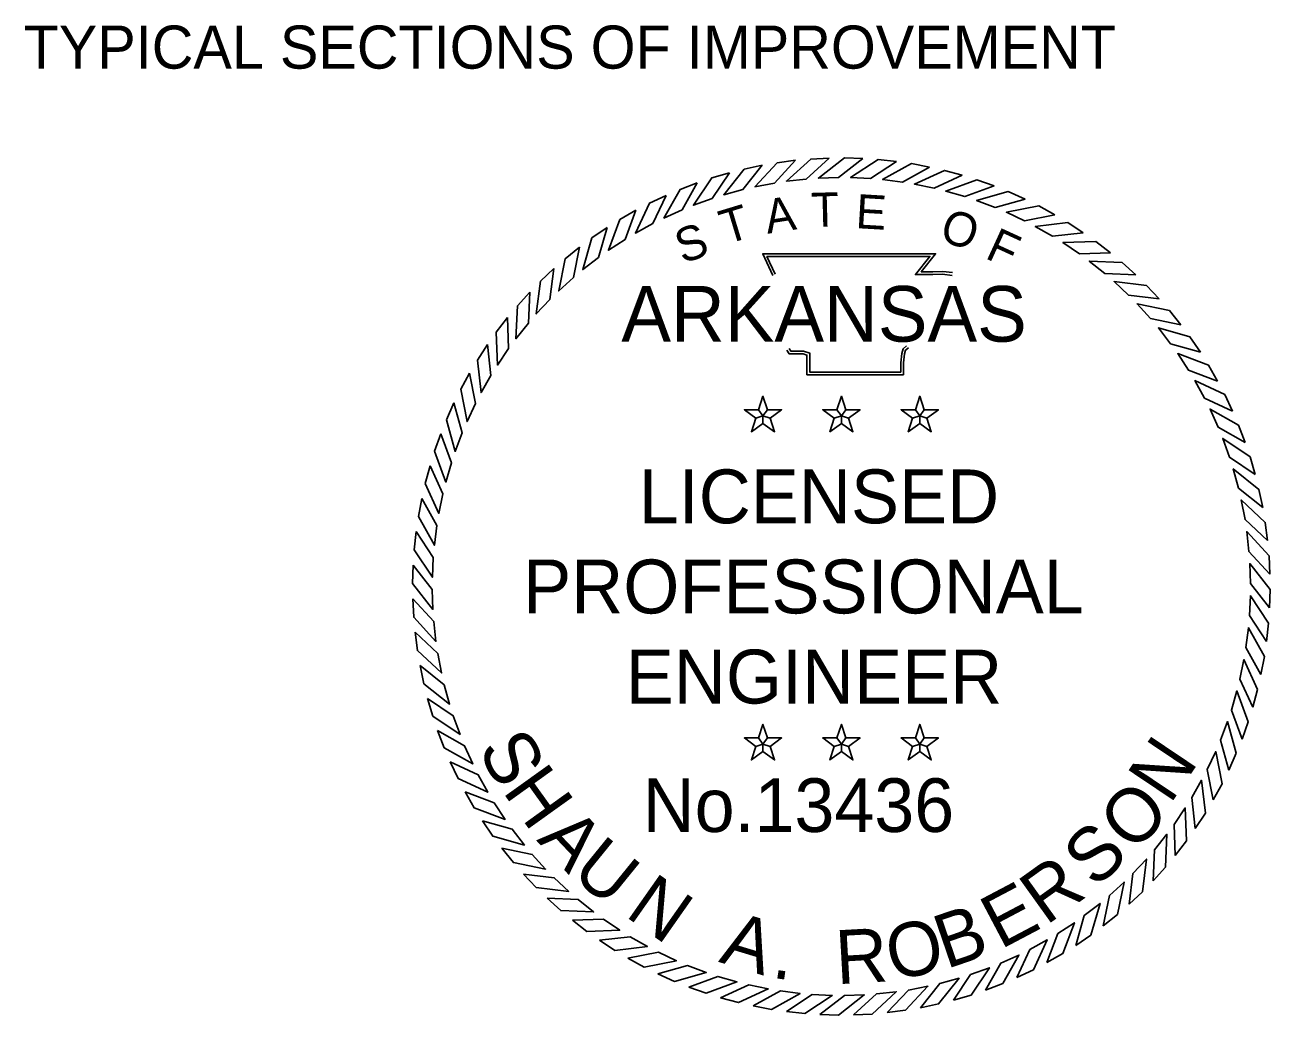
# Model space of a CAD drawing. Extents: x 1001270 to 1003428, y 1840152 to 1842912.
# Drawn here: x 1001411.14 to 1001428.47, y 1840237.95 to 1840251.73 of the extents above; entities that cross this region are included whole.
import ezdxf

# ---------------------------------------------------------------- set-up
doc = ezdxf.new("R2010")
doc.units = 0
doc.layers.add('1', color=7, linetype='Continuous')
doc.layers.add('G-ANNO-SYMB', color=7, linetype='Continuous')

msp = doc.modelspace()

# ---------------------------------------------------------------- linework, layer by layer
at = {"layer": 'G-ANNO-SYMB'}
for points in [[(1001421.401, 1840249.777), (1001421.15, 1840249.724), (1001420.865, 1840249.367), (1001421.132, 1840249.44)], [(1001421.864, 1840249.846), (1001421.61, 1840249.813), (1001421.298, 1840249.478), (1001421.57, 1840249.53)], [(1001422.332, 1840249.877), (1001422.075, 1840249.864), (1001421.738, 1840249.556), (1001422.014, 1840249.586)], [(1001422.8, 1840249.872), (1001422.544, 1840249.88), (1001422.183, 1840249.598), (1001422.46, 1840249.607)], [(1001423.267, 1840249.831), (1001423.012, 1840249.858), (1001422.63, 1840249.606), (1001422.907, 1840249.593)], [(1001423.729, 1840249.752), (1001423.476, 1840249.8), (1001423.076, 1840249.578), (1001423.351, 1840249.543)], [(1001420.944, 1840249.673), (1001420.698, 1840249.6), (1001420.442, 1840249.221), (1001420.703, 1840249.315)], [(1001424.183, 1840249.638), (1001423.935, 1840249.705), (1001423.519, 1840249.515), (1001423.791, 1840249.459)], [(1001424.627, 1840249.489), (1001424.385, 1840249.575), (1001423.955, 1840249.418), (1001424.222, 1840249.341)], [(1001420.497, 1840249.533), (1001420.257, 1840249.441), (1001420.032, 1840249.043), (1001420.285, 1840249.158)], [(1001425.058, 1840249.305), (1001424.823, 1840249.41), (1001424.383, 1840249.287), (1001424.642, 1840249.19)], [(1001420.063, 1840249.358), (1001419.831, 1840249.248), (1001419.637, 1840248.834), (1001419.88, 1840248.967)], [(1001419.643, 1840249.15), (1001419.42, 1840249.022), (1001419.26, 1840248.594), (1001419.492, 1840248.746)], [(1001425.473, 1840249.088), (1001425.248, 1840249.211), (1001424.799, 1840249.123), (1001425.049, 1840249.005)], [(1001419.241, 1840248.909), (1001419.029, 1840248.765), (1001418.903, 1840248.325), (1001419.122, 1840248.495)], [(1001425.869, 1840248.839), (1001425.655, 1840248.979), (1001425.2, 1840248.927), (1001425.441, 1840248.79)], [(1001426.246, 1840248.559), (1001426.042, 1840248.716), (1001425.585, 1840248.7), (1001425.815, 1840248.544)], [(1001418.859, 1840248.638), (1001418.659, 1840248.477), (1001418.568, 1840248.029), (1001418.773, 1840248.216)], [(1001426.598, 1840248.251), (1001426.408, 1840248.423), (1001425.951, 1840248.443), (1001426.168, 1840248.27)], [(1001418.5, 1840248.338), (1001418.313, 1840248.162), (1001418.257, 1840247.708), (1001418.447, 1840247.91)], [(1001426.926, 1840247.916), (1001426.75, 1840248.103), (1001426.296, 1840248.159), (1001426.498, 1840247.969)], [(1001418.165, 1840248.01), (1001417.993, 1840247.82), (1001417.973, 1840247.363), (1001418.146, 1840247.579)], [(1001427.227, 1840247.557), (1001427.066, 1840247.757), (1001426.617, 1840247.848), (1001426.804, 1840247.643)], [(1001417.857, 1840247.657), (1001417.7, 1840247.454), (1001417.716, 1840246.997), (1001417.872, 1840247.226)], [(1001427.498, 1840247.175), (1001427.353, 1840247.387), (1001426.913, 1840247.513), (1001427.083, 1840247.294)], [(1001417.577, 1840247.281), (1001417.437, 1840247.066), (1001417.489, 1840246.612), (1001417.626, 1840246.853)], [(1001427.738, 1840246.773), (1001427.611, 1840246.996), (1001427.182, 1840247.156), (1001427.334, 1840246.924)], [(1001417.328, 1840246.884), (1001417.205, 1840246.659), (1001417.293, 1840246.21), (1001417.411, 1840246.461)], [(1001427.946, 1840246.353), (1001427.837, 1840246.585), (1001427.422, 1840246.779), (1001427.556, 1840246.536)], [(1001417.111, 1840246.469), (1001417.006, 1840246.235), (1001417.129, 1840245.794), (1001417.226, 1840246.054)], [(1001421.411, 1840246.289), (1001421.472, 1840246.374), (1001421.411, 1840246.562), (1001421.35, 1840246.374)], [(1001422.502, 1840246.289), (1001422.563, 1840246.374), (1001422.502, 1840246.562), (1001422.441, 1840246.374)], [(1001423.593, 1840246.289), (1001423.654, 1840246.374), (1001423.593, 1840246.562), (1001423.532, 1840246.374)], [(1001421.411, 1840246.289), (1001421.35, 1840246.374), (1001421.152, 1840246.374), (1001421.312, 1840246.257)], [(1001421.411, 1840246.289), (1001421.312, 1840246.257), (1001421.251, 1840246.069), (1001421.411, 1840246.185)], [(1001421.411, 1840246.289), (1001421.51, 1840246.257), (1001421.671, 1840246.374), (1001421.472, 1840246.374)], [(1001421.411, 1840246.289), (1001421.411, 1840246.185), (1001421.572, 1840246.069), (1001421.51, 1840246.257)], [(1001422.502, 1840246.289), (1001422.441, 1840246.374), (1001422.243, 1840246.374), (1001422.403, 1840246.257)], [(1001422.502, 1840246.289), (1001422.403, 1840246.257), (1001422.342, 1840246.069), (1001422.502, 1840246.185)], [(1001422.502, 1840246.289), (1001422.601, 1840246.257), (1001422.762, 1840246.374), (1001422.563, 1840246.374)], [(1001422.502, 1840246.289), (1001422.502, 1840246.185), (1001422.662, 1840246.069), (1001422.601, 1840246.257)], [(1001423.593, 1840246.289), (1001423.532, 1840246.374), (1001423.334, 1840246.374), (1001423.494, 1840246.257)], [(1001423.593, 1840246.289), (1001423.494, 1840246.257), (1001423.433, 1840246.069), (1001423.593, 1840246.185)], [(1001423.593, 1840246.289), (1001423.692, 1840246.257), (1001423.852, 1840246.374), (1001423.654, 1840246.374)], [(1001423.593, 1840246.289), (1001423.593, 1840246.185), (1001423.753, 1840246.069), (1001423.692, 1840246.257)], [(1001428.121, 1840245.919), (1001428.03, 1840246.159), (1001427.632, 1840246.384), (1001427.746, 1840246.131)], [(1001416.927, 1840246.038), (1001416.841, 1840245.797), (1001416.998, 1840245.367), (1001417.075, 1840245.633)], [(1001428.261, 1840245.472), (1001428.189, 1840245.718), (1001427.81, 1840245.974), (1001427.904, 1840245.713)], [(1001416.778, 1840245.594), (1001416.711, 1840245.347), (1001416.901, 1840244.931), (1001416.957, 1840245.202)], [(1001428.366, 1840245.015), (1001428.313, 1840245.266), (1001427.955, 1840245.551), (1001428.028, 1840245.284)], [(1001416.664, 1840245.14), (1001416.616, 1840244.888), (1001416.838, 1840244.488), (1001416.873, 1840244.763)], [(1001428.434, 1840244.552), (1001428.401, 1840244.806), (1001428.067, 1840245.118), (1001428.119, 1840244.846)], [(1001416.585, 1840244.678), (1001416.558, 1840244.423), (1001416.81, 1840244.042), (1001416.823, 1840244.319)], [(1001428.466, 1840244.084), (1001428.453, 1840244.341), (1001428.144, 1840244.678), (1001428.174, 1840244.402)], [(1001416.544, 1840244.212), (1001416.536, 1840243.955), (1001416.818, 1840243.595), (1001416.809, 1840243.872)], [(1001428.461, 1840243.616), (1001428.468, 1840243.872), (1001428.186, 1840244.233), (1001428.195, 1840243.956)], [(1001416.539, 1840243.743), (1001416.552, 1840243.487), (1001416.86, 1840243.15), (1001416.83, 1840243.425)], [(1001428.419, 1840243.149), (1001428.446, 1840243.404), (1001428.194, 1840243.786), (1001428.181, 1840243.509)], [(1001428.341, 1840242.687), (1001428.388, 1840242.94), (1001428.166, 1840243.34), (1001428.132, 1840243.065)], [(1001416.57, 1840243.276), (1001416.603, 1840243.022), (1001416.938, 1840242.71), (1001416.886, 1840242.982)], [(1001416.639, 1840242.813), (1001416.692, 1840242.561), (1001417.049, 1840242.277), (1001416.976, 1840242.544)], [(1001428.226, 1840242.233), (1001428.293, 1840242.481), (1001428.104, 1840242.897), (1001428.048, 1840242.625)], [(1001416.743, 1840242.356), (1001416.816, 1840242.11), (1001417.195, 1840241.854), (1001417.101, 1840242.115)], [(1001428.077, 1840241.789), (1001428.163, 1840242.031), (1001428.007, 1840242.461), (1001427.93, 1840242.194)], [(1001421.411, 1840241.721), (1001421.472, 1840241.806), (1001421.411, 1840241.994), (1001421.35, 1840241.806)], [(1001422.502, 1840241.721), (1001422.563, 1840241.806), (1001422.502, 1840241.994), (1001422.441, 1840241.806)], [(1001423.593, 1840241.721), (1001423.654, 1840241.806), (1001423.593, 1840241.994), (1001423.532, 1840241.806)], [(1001427.893, 1840241.358), (1001427.998, 1840241.593), (1001427.876, 1840242.033), (1001427.778, 1840241.774)], [(1001416.883, 1840241.909), (1001416.975, 1840241.669), (1001417.373, 1840241.444), (1001417.258, 1840241.697)], [(1001421.411, 1840241.721), (1001421.35, 1840241.806), (1001421.152, 1840241.806), (1001421.312, 1840241.689)], [(1001421.411, 1840241.721), (1001421.51, 1840241.689), (1001421.671, 1840241.806), (1001421.472, 1840241.806)], [(1001422.502, 1840241.721), (1001422.441, 1840241.806), (1001422.243, 1840241.806), (1001422.403, 1840241.689)], [(1001422.502, 1840241.721), (1001422.601, 1840241.689), (1001422.762, 1840241.806), (1001422.563, 1840241.806)], [(1001423.593, 1840241.721), (1001423.532, 1840241.806), (1001423.334, 1840241.806), (1001423.494, 1840241.689)], [(1001423.593, 1840241.721), (1001423.692, 1840241.689), (1001423.852, 1840241.806), (1001423.654, 1840241.806)], [(1001421.411, 1840241.721), (1001421.312, 1840241.689), (1001421.251, 1840241.501), (1001421.411, 1840241.617)], [(1001421.411, 1840241.721), (1001421.411, 1840241.617), (1001421.572, 1840241.501), (1001421.51, 1840241.689)], [(1001422.502, 1840241.721), (1001422.403, 1840241.689), (1001422.342, 1840241.501), (1001422.502, 1840241.617)], [(1001422.502, 1840241.721), (1001422.502, 1840241.617), (1001422.662, 1840241.501), (1001422.601, 1840241.689)], [(1001423.593, 1840241.721), (1001423.494, 1840241.689), (1001423.433, 1840241.501), (1001423.593, 1840241.617)], [(1001423.593, 1840241.721), (1001423.593, 1840241.617), (1001423.753, 1840241.501), (1001423.692, 1840241.689)], [(1001427.676, 1840240.943), (1001427.799, 1840241.168), (1001427.712, 1840241.617), (1001427.594, 1840241.367)], [(1001417.058, 1840241.474), (1001417.168, 1840241.242), (1001417.582, 1840241.049), (1001417.449, 1840241.292)], [(1001427.427, 1840240.547), (1001427.567, 1840240.761), (1001427.515, 1840241.216), (1001427.378, 1840240.975)], [(1001417.266, 1840241.055), (1001417.394, 1840240.832), (1001417.822, 1840240.672), (1001417.67, 1840240.904)], [(1001427.148, 1840240.17), (1001427.304, 1840240.374), (1001427.288, 1840240.831), (1001427.133, 1840240.601)], [(1001417.507, 1840240.653), (1001417.651, 1840240.441), (1001418.091, 1840240.315), (1001417.921, 1840240.534)], [(1001426.84, 1840239.818), (1001427.012, 1840240.008), (1001427.032, 1840240.465), (1001426.858, 1840240.248)], [(1001417.778, 1840240.271), (1001417.939, 1840240.071), (1001418.387, 1840239.98), (1001418.2, 1840240.185)], [(1001426.505, 1840239.49), (1001426.691, 1840239.666), (1001426.747, 1840240.12), (1001426.557, 1840239.918)], [(1001418.078, 1840239.911), (1001418.254, 1840239.725), (1001418.708, 1840239.669), (1001418.506, 1840239.859)], [(1001426.145, 1840239.189), (1001426.345, 1840239.35), (1001426.436, 1840239.799), (1001426.231, 1840239.612)], [(1001418.406, 1840239.576), (1001418.596, 1840239.404), (1001419.053, 1840239.384), (1001418.837, 1840239.558)], [(1001425.763, 1840238.918), (1001425.975, 1840239.063), (1001426.101, 1840239.503), (1001425.882, 1840239.333)], [(1001418.759, 1840239.268), (1001418.962, 1840239.112), (1001419.419, 1840239.128), (1001419.19, 1840239.283)], [(1001425.361, 1840238.678), (1001425.584, 1840238.805), (1001425.744, 1840239.234), (1001425.512, 1840239.082)], [(1001419.135, 1840238.989), (1001419.35, 1840238.849), (1001419.804, 1840238.901), (1001419.563, 1840239.038)], [(1001424.942, 1840238.47), (1001425.174, 1840238.579), (1001425.367, 1840238.994), (1001425.124, 1840238.86)], [(1001419.532, 1840238.74), (1001419.757, 1840238.617), (1001420.206, 1840238.704), (1001419.955, 1840238.822)], [(1001424.507, 1840238.295), (1001424.747, 1840238.386), (1001424.972, 1840238.784), (1001424.719, 1840238.67)], [(1001419.947, 1840238.523), (1001420.181, 1840238.418), (1001420.621, 1840238.54), (1001420.362, 1840238.638)], [(1001420.378, 1840238.339), (1001420.619, 1840238.253), (1001421.049, 1840238.409), (1001420.783, 1840238.486)], [(1001424.06, 1840238.155), (1001424.306, 1840238.227), (1001424.562, 1840238.606), (1001424.301, 1840238.512)], [(1001420.822, 1840238.189), (1001421.069, 1840238.123), (1001421.485, 1840238.312), (1001421.214, 1840238.368)], [(1001423.14, 1840237.982), (1001423.394, 1840238.015), (1001423.706, 1840238.349), (1001423.434, 1840238.297)], [(1001423.603, 1840238.05), (1001423.855, 1840238.103), (1001424.139, 1840238.461), (1001423.872, 1840238.388)], [(1001421.276, 1840238.075), (1001421.528, 1840238.028), (1001421.928, 1840238.25), (1001421.653, 1840238.284)], [(1001421.738, 1840237.997), (1001421.993, 1840237.97), (1001422.374, 1840238.222), (1001422.097, 1840238.235)], [(1001422.204, 1840237.955), (1001422.461, 1840237.948), (1001422.821, 1840238.23), (1001422.544, 1840238.221)], [(1001422.673, 1840237.95), (1001422.929, 1840237.963), (1001423.266, 1840238.272), (1001422.991, 1840238.242)]]:
    msp.add_lwpolyline(points, close=True, dxfattribs=at)
for points in [[(1001421.546, 1840248.244), (1001421.407, 1840248.545), (1001423.814, 1840248.546), (1001423.613, 1840248.294), (1001423.776, 1840248.296), (1001423.913, 1840248.298), (1001424.049, 1840248.283)], [(1001421.581, 1840248.26), (1001421.467, 1840248.507), (1001423.735, 1840248.508), (1001423.533, 1840248.255), (1001423.777, 1840248.258), (1001423.911, 1840248.26), (1001424.045, 1840248.245)], [(1001423.434, 1840247.235), (1001423.393, 1840247.202), (1001423.38, 1840247.152), (1001423.366, 1840247.027), (1001423.366, 1840246.861), (1001422.023, 1840246.861), (1001422.023, 1840247.086), (1001422.023, 1840247.135), (1001421.968, 1840247.152), (1001421.777, 1840247.152), (1001421.743, 1840247.204)], [(1001423.41, 1840247.265), (1001423.36, 1840247.224), (1001423.342, 1840247.159), (1001423.328, 1840247.029), (1001423.328, 1840246.899), (1001422.061, 1840246.899), (1001422.061, 1840247.086), (1001422.061, 1840247.164), (1001421.974, 1840247.19), (1001421.798, 1840247.19), (1001421.775, 1840247.225)]]:
    msp.add_lwpolyline(points, dxfattribs=at)

# ---------------------------------------------------------------- texts
at = {"layer": '1'}
msp.add_text('TYPICAL SECTIONS OF IMPROVEMENT', height=0.6, dxfattribs=at).set_placement((1001411.122, 1840251.122))
at = {"layer": 'G-ANNO-SYMB'}
for s, height, rotation, p in [('T', 0.475, 1.4789, (1001422.086, 1840248.918)), ('T', 0.475, 16.9015, (1001420.897, 1840248.673)), ('A', 0.475, 8.6788, (1001421.473, 1840248.823)), ('E', 0.475, 356.672, (1001422.693, 1840248.903)), ('O', 0.475, 341.2218, (1001423.846, 1840248.74)), ('S', 0.475, 19.7726, (1001420.293, 1840248.402)), ('F', 0.475, 335.3628, (1001424.486, 1840248.49)), ('ARKANSAS', 0.7747, 360, (1001419.44, 1840247.322)), ('LICENSED', 0.75, 360, (1001419.681, 1840244.793)), ('PROFESSIONAL', 0.75, 360, (1001418.074, 1840243.539)), ('ENGINEER', 0.75, 360, (1001419.502, 1840242.285)), ('S', 0.75, 298.1636, (1001417.434, 1840241.654)), ('N', 0.75, 56.1007, (1001427.076, 1840240.87)), ('H', 0.75, 305.619, (1001417.776, 1840241.066)), ('No.13436', 0.747, 360, (1001419.739, 1840240.497)), ('O', 0.75, 44.7757, (1001426.555, 1840240.195)), ('A', 0.75, 313.4472, (1001418.252, 1840240.382)), ('S', 0.75, 43.4878, (1001426.04, 1840239.698)), ('U', 0.75, 320.9026, (1001418.72, 1840239.893)), ('R', 0.75, 35.6597, (1001425.35, 1840239.188)), ('N', 0.75, 324.9326, (1001419.476, 1840239.334)), ('E', 0.75, 27.8315, (1001424.716, 1840238.856)), ('B', 0.75, 18.885, (1001423.959, 1840238.585)), ('A', 0.75, 343.0991, (1001420.783, 1840238.691)), ('O', 0.75, 11.4296, (1001423.207, 1840238.426)), ('R', 0.75, 3.2287, (1001422.44, 1840238.377)), ('.', 0.75, 351.3, (1001421.52, 1840238.472))]:
    msp.add_text(s, height=height, rotation=rotation, dxfattribs=at).set_placement(p)

doc.saveas('drawing.dxf')
